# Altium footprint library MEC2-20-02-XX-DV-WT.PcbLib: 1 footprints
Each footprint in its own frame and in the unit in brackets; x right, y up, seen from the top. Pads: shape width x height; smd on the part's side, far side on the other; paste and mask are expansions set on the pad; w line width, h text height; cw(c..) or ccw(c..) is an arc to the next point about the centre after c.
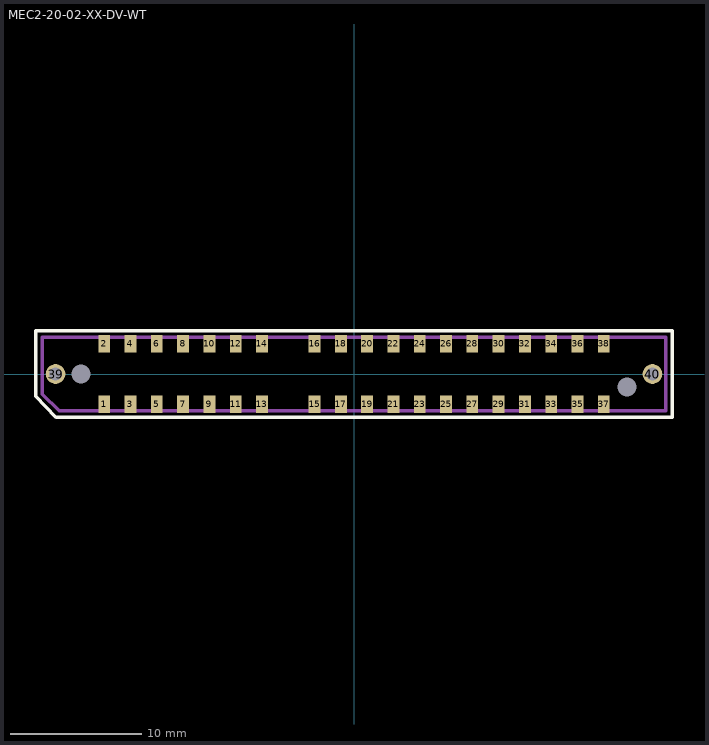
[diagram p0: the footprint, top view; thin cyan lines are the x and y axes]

## MEC2-20-02-XX-DV-WT [mm]
pads (42):
  rect 0.9x1.35 smd mask+0.05: 1(-19,-2.295) 2(-19,2.295) 3(-17,-2.295) 4(-17,2.295) 5(-15,-2.295) 6(-15,2.295) 7(-13,-2.295) 8(-13,2.295) 9(-11,-2.295) 10(-11,2.295) 11(-9,-2.295) 12(-9,2.295) 13(-7,-2.295) 14(-7,2.295) 15(-3,-2.295) 16(-3,2.295) 17(-1,-2.295) 18(-1,2.295) 19(1,-2.295) 20(1,2.295) 21(3,-2.295) 22(3,2.295) 23(5,-2.295) 24(5,2.295) 25(7,-2.295) 26(7,2.295) 27(9,-2.295) 28(9,2.295) 29(11,-2.295) 30(11,2.295) 31(13,-2.295) 32(13,2.295) 33(15,-2.295) 34(15,2.295) 35(17,-2.295) 36(17,2.295) 37(19,-2.295) 38(19,2.295)
  round 1.5 hole 1 mask+0.075: 39(-22.7,0) 40(22.7,0)
  round 0 hole 1.45 unplated: 41(-20.75,0) 42(20.75,-1)
Top Overlay:
  lines w0.254: -24.2,-1.7 -24.2,3.3 24.2,3.3 24.2,-3.3 -22.67,-3.3 -24.2,-1.7
Mechanical 1:
  lines w0.254: -23.7,-1.53 -23.7,2.8 23.7,2.8 23.7,-2.8 -22.43,-2.8 -23.7,-1.53
  text "J1" at -0.446,-0.457 h0.76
